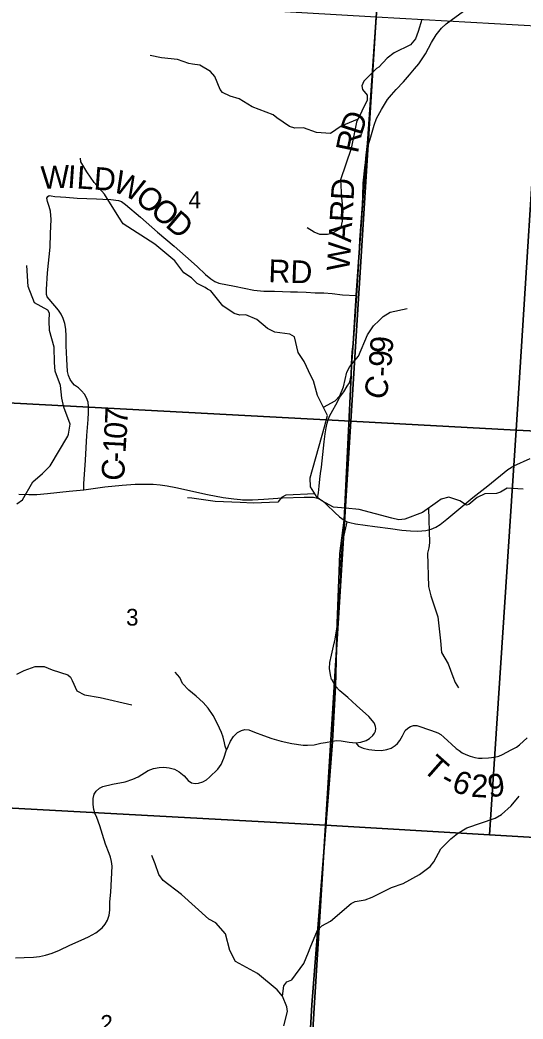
# Model space of a CAD drawing. Extents: x 1878108 to 2183446, y 146837 to 508383.
# Drawn here: x 2045522 to 2052165, y 348659 to 361848 of the extents above; entities that cross this region are included whole.
import ezdxf

# ---------------------------------------------------------------- set-up
doc = ezdxf.new("R2010")
doc.units = 0
for name, color, linetype in [('GM_X_County_Road', 7, 'Continuous'), ('GM_X_County_Road_Text', 7, 'Continuous'), ('GM_X_Minor_River', 7, 'Continuous'), ('GM_X_Section', 7, 'Continuous'), ('GM_X_Section_Text', 7, 'Continuous'), ('GM_X_State_Route', 7, 'Continuous'), ('GM_X_Township', 7, 'Continuous'), ('GM_X_Township_Road', 7, 'Continuous'), ('GM_X_Township_Road_Text', 7, 'Continuous'), ('GM_X_Township_ROW', 7, 'Continuous')]:
    doc.layers.add(name, color=color, linetype=linetype)

msp = doc.modelspace()

# ---------------------------------------------------------------- linework, layer by layer
at = {"layer": 'GM_X_County_Road'}
for points in [[(2050115, 360147), (2050122, 360189), (2050154, 360306), (2050199, 360460), (2050232, 360547), (2050295, 360666), (2050375, 360797), (2050429, 360861), (2050491, 360928), (2050587, 361033), (2050664, 361124), (2050731, 361202), (2050789, 361269), (2050876, 361401), (2050958, 361550), (2051020, 361653), (2051090, 361739), (2051151, 361798), (2051215, 361846), (2051377, 361964)], [(2050048, 359520), (2050055, 359694), (2050082, 359934), (2050097, 360034), (2050115, 360147)], [(2046364, 355647), (2046367, 355723), (2046387, 356036), (2046403, 356363), (2046424, 356573), (2046427, 356667), (2046429, 356746), (2046424, 356802), (2046402, 356860), (2046372, 356910), (2046333, 356954), (2046293, 356990), (2046244, 357029), (2046214, 357058), (2046184, 357100), (2046164, 357153), (2046151, 357207), (2046141, 357371), (2046134, 357545), (2046130, 357672), (2046128, 357765), (2046113, 357841), (2046094, 357908), (2046066, 357964), (2046032, 358019), (2045906, 358162), (2045883, 358193), (2045873, 358224), (2045872, 358290), (2045887, 358510), (2045919, 358849), (2045927, 359031), (2045932, 359215), (2045925, 359324), (2045907, 359385), (2045886, 359453), (2045877, 359494), (2045888, 359518), (2045907, 359530), (2045936, 359528), (2045981, 359518), (2046059, 359512), (2046129, 359510), (2046277, 359497), (2046531, 359485), (2046615, 359484), (2046720, 359477), (2046821, 359464), (2046864, 359453), (2046915, 359414), (2047112, 359245), (2047338, 359047), (2047557, 358863), (2047709, 358732), (2047862, 358593), (2047973, 358489), (2048041, 358432), (2048097, 358394), (2048147, 358375), (2048355, 358332), (2048610, 358282), (2048743, 358268), (2048883, 358267), (2049095, 358257), (2049189, 358257), (2049303, 358253), (2049418, 358246), (2049533, 358245), (2049644, 358236), (2049783, 358220), (2049963, 358209), (2049972, 358208)], [(2050005, 358838), (2050011, 358945), (2050044, 359411), (2050048, 359520)], [(2049972, 358208), (2049995, 358634), (2050002, 358765), (2050005, 358838)], [(2049898, 357201), (2049900, 357246), (2049909, 357346), (2049919, 357467), (2049935, 357701), (2049972, 358208)], [(2049452, 355537), (2049464, 355604), (2049472, 355695), (2049482, 355784), (2049491, 355861), (2049502, 355943), (2049540, 356278), (2049554, 356383), (2049565, 356463), (2049577, 356527), (2049590, 356571), (2049609, 356616), (2049652, 356695), (2049692, 356769), (2049748, 356867), (2049798, 356941), (2049843, 357012), (2049872, 357058), (2049887, 357110), (2049895, 357156), (2049898, 357201)], [(2049670, 353619), (2049678, 353653), (2049708, 353808), (2049723, 353970), (2049737, 354113), (2049753, 354388), (2049761, 354563), (2049767, 354776), (2049782, 354914), (2049803, 355046), (2049835, 355183), (2049844, 355222)], [(2049638, 353143), (2049623, 353205), (2049611, 353286), (2049613, 353364), (2049634, 353462), (2049670, 353619)], [(2049958, 352306), (2050021, 352314), (2050092, 352336), (2050138, 352364), (2050182, 352403), (2050205, 352433), (2050217, 352460), (2050220, 352495), (2050216, 352519), (2050210, 352547), (2050198, 352571), (2050129, 352653), (2049966, 352799), (2049851, 352903), (2049744, 352990), (2049687, 353053), (2049639, 353140), (2049638, 353143)], [(2048293, 352304), (2048303, 352326), (2048343, 352391), (2048396, 352441), (2048446, 352469), (2048492, 352480), (2048543, 352478), (2048620, 352447), (2048739, 352400), (2048847, 352361), (2048969, 352328), (2049111, 352296), (2049260, 352276), (2049321, 352276), (2049408, 352281), (2049494, 352299), (2049555, 352311)], [(2045463, 349468), (2045577, 349472), (2045699, 349474), (2045779, 349484), (2045859, 349501), (2045947, 349529), (2046046, 349569), (2046182, 349635), (2046329, 349702), (2046429, 349746), (2046522, 349797), (2046608, 349862), (2046649, 349910), (2046679, 349964), (2046700, 350030), (2046709, 350095), (2046710, 350208), (2046723, 350333), (2046730, 350507), (2046738, 350677), (2046732, 350740), (2046719, 350794), (2046699, 350845), (2046650, 350968), (2046612, 351094), (2046576, 351210), (2046535, 351319), (2046509, 351379), (2046496, 351425), (2046487, 351493), (2046487, 351570), (2046503, 351629), (2046528, 351669), (2046570, 351707), (2046617, 351728), (2046746, 351758), (2046912, 351792), (2047013, 351825), (2047081, 351857), (2047217, 351940), (2047287, 351966), (2047362, 351980), (2047421, 351982), (2047494, 351976), (2047564, 351956), (2047625, 351924), (2047689, 351868), (2047745, 351807), (2047788, 351779), (2047834, 351769), (2047879, 351775), (2047936, 351791), (2047983, 351818), (2048025, 351850), (2048135, 351958), (2048181, 352018), (2048213, 352101), (2048251, 352211), (2048266, 352242), (2048275, 352268), (2048293, 352304)], [(2049555, 352311), (2049648, 352329), (2049701, 352336), (2049763, 352332), (2049867, 352316), (2049958, 352306)]]:
    msp.add_lwpolyline(points, dxfattribs=at)
at = {"layer": 'GM_X_Minor_River'}
for points in [[(2050827, 361852), (2050780, 361694), (2050746, 361599), (2050677, 361519), (2050464, 361414), (2050372, 361344), (2050259, 361226), (2050229, 361208), (2050062, 361038), (2050038, 360980), (2050044, 360928), (2050109, 360853), (2050105, 360787), (2049968, 360498), (2049894, 360153), (2049754, 359736), (2049767, 359501), (2049787, 359338), (2049778, 359194), (2049753, 359097), (2049641, 359028), (2049585, 359018), (2049483, 359018), (2049407, 359047), (2049313, 359106)], [(2049976, 360532), (2049765, 360445), (2049621, 360351), (2049438, 360364), (2049268, 360425), (2049150, 360418), (2049080, 360442), (2048914, 360557), (2048864, 360596), (2048590, 360701), (2048416, 360805), (2048296, 360843), (2048196, 360892), (2048165, 360928), (2048093, 361101), (2048037, 361168), (2047896, 361253), (2047801, 361263), (2047753, 361274), (2047603, 361328), (2047391, 361347), (2047243, 361380)], [(2052167, 355652), (2051957, 355665), (2051868, 355613), (2051816, 355598), (2051660, 355594), (2051561, 355545), (2051451, 355451), (2051419, 355441), (2051331, 355501), (2051185, 355548), (2051083, 355521), (2051036, 355487), (2050839, 355347), (2050603, 355256), (2050527, 355250), (2050433, 355270), (2050002, 355385), (2049820, 355404), (2049664, 355417), (2049510, 355500), (2049446, 355542), (2049359, 355683), (2049355, 355802), (2049544, 356476), (2049585, 356626), (2049452, 356892), (2049400, 357083), (2049361, 357151), (2049273, 357338), (2049196, 357457), (2049148, 357664), (2049085, 357701), (2048888, 357726), (2048792, 357776), (2048649, 357895), (2048505, 357954), (2048425, 357953), (2048352, 357971), (2048201, 358074), (2048043, 358274), (2047999, 358294), (2047967, 358318), (2047863, 358369), (2047788, 358444), (2047686, 358510), (2047568, 358668), (2047303, 358890), (2046885, 359155), (2046827, 359243), (2046638, 359549), (2046503, 359701), (2046405, 359842), (2046324, 359973), (2046320, 360023)], [(2045481, 355460), (2045556, 355514), (2045691, 355752), (2045820, 355862), (2045920, 355964), (2046156, 356354), (2046164, 356382), (2046183, 356513), (2046100, 356738), (2046076, 356855), (2046055, 357022), (2045985, 357211), (2045976, 357327), (2045975, 357528), (2045910, 357747), (2045906, 357876), (2045911, 357978), (2045891, 358016), (2045715, 358112), (2045632, 358331), (2045613, 358606)], [(2049530, 356736), (2049686, 356820), (2049744, 356884), (2049795, 357003), (2049840, 357199), (2049878, 357273), (2049993, 357409), (2050110, 357692), (2050189, 357810), (2050265, 357880), (2050318, 357934), (2050412, 357990), (2050636, 358041)], [(2049414, 355591), (2049033, 355573), (2048975, 355543), (2048929, 355483), (2048602, 355468), (2048430, 355477), (2048101, 355491), (2047791, 355534), (2047733, 355541)], [(2050917, 355402), (2050932, 354947), (2050922, 354881), (2050905, 354808), (2050918, 354369), (2050947, 354244), (2051038, 353968), (2051075, 353653), (2051090, 353500), (2051178, 353349), (2051239, 353180), (2051267, 353100), (2051315, 353033)], [(2045480, 353210), (2045576, 353262), (2045723, 353312), (2045843, 353315), (2045945, 353267), (2046153, 353205), (2046189, 353171), (2046211, 353129), (2046274, 352990), (2046374, 352939), (2046580, 352902), (2046999, 352808)], [(2049007, 348569), (2049053, 348758), (2049048, 348822), (2048987, 348961), (2049005, 349098), (2049048, 349149), (2049114, 349175), (2049270, 349394), (2049334, 349543), (2049353, 349601), (2049453, 349833), (2049510, 349890), (2049622, 349951), (2049897, 350185), (2049949, 350212), (2050081, 350232), (2050173, 350269), (2050426, 350396), (2050583, 350450), (2050796, 350567), (2050937, 350675), (2050987, 350733), (2051081, 350905), (2051213, 351037), (2051301, 351110), (2051422, 351182), (2051797, 351310), (2051879, 351359), (2052007, 351473), (2052116, 351603)], [(2048987, 348963), (2048917, 349043), (2048658, 349262), (2048366, 349419), (2048292, 349563), (2048237, 349785), (2048109, 349930), (2048015, 349979), (2047654, 350302), (2047415, 350487), (2047356, 350567), (2047308, 350707), (2047263, 350817)]]:
    msp.add_lwpolyline(points, dxfattribs=at)
at = {"layer": 'GM_X_Section'}
for points in [[(2044786, 362212), (2050224, 361889), (2049893, 356551), (2044454, 356844), (2044518, 357870), (2044650, 360006)], [(2050224, 361889), (2052412, 361767), (2052076, 356435), (2049893, 356551)], [(2052412, 361767), (2054629, 361642), (2054256, 356327), (2052076, 356435)], [(2044454, 356844), (2049893, 356551), (2049557, 351218), (2044125, 351515), (2044378, 355609)], [(2052076, 356435), (2051723, 351091), (2049557, 351218), (2049893, 356551)], [(2054256, 356327), (2053887, 350963), (2051723, 351091), (2052076, 356435)], [(2044125, 351515), (2049557, 351218), (2049224, 345820), (2043762, 346145)], [(2051723, 351091), (2053887, 350963), (2054841, 350907), (2054872, 350905), (2054518, 345558), (2049224, 345820), (2049557, 351218)]]:
    msp.add_lwpolyline(points, close=True, dxfattribs=at)
at = {"layer": 'GM_X_State_Route'}
for points in [[(2049399, 355547), (2049452, 355537), (2049481, 355523), (2049511, 355503), (2049570, 355452), (2049680, 355348), (2049743, 355289), (2049804, 355245), (2049844, 355222), (2049878, 355212), (2049953, 355196), (2050209, 355163), (2050413, 355133), (2050566, 355111), (2050680, 355103), (2050776, 355098), (2050881, 355109), (2050950, 355126), (2051015, 355152), (2051070, 355189), (2051158, 355260), (2051504, 355546), (2051699, 355700), (2051965, 355912), (2052044, 355960), (2052259, 356060)], [(2045505, 355587), (2045639, 355582), (2045743, 355584), (2045884, 355595), (2046171, 355627), (2046364, 355647), (2046642, 355683), (2046872, 355708), (2047041, 355720), (2047151, 355722), (2047282, 355720), (2047373, 355712), (2047467, 355698), (2047579, 355677), (2048000, 355583), (2048205, 355544), (2048345, 355525), (2048434, 355518)], [(2048434, 355518), (2048461, 355515), (2048591, 355515), (2048741, 355523), (2048987, 355539), (2049276, 355550), (2049388, 355549), (2049399, 355547)]]:
    msp.add_lwpolyline(points, dxfattribs=at)
at = {"layer": 'GM_X_Township'}
for points in [[(2031084, 368365), (2039539, 367898), (2040525, 367845), (2042889, 367717), (2045115, 367597), (2048789, 367394), (2050600, 367297), (2050350, 363670), (2050111, 360216), (2050089, 360025), (2049963, 358214), (2049921, 357571), (2049907, 357468), (2049898, 357303), (2049895, 357156), (2049804, 355245), (2049744, 354805), (2049709, 353880), (2049687, 353053), (2049647, 352324), (2049375, 348847), (2049004, 342247)], [(2049004, 342247), (2049375, 348847), (2049647, 352324), (2049687, 353053), (2049709, 353880), (2049744, 354805), (2049804, 355245), (2049895, 357156), (2049898, 357303), (2049907, 357468), (2049921, 357571), (2049963, 358214), (2050089, 360025), (2050111, 360216), (2050350, 363670), (2050600, 367297), (2051071, 367290), (2053261, 367127)]]:
    msp.add_lwpolyline(points, dxfattribs=at)
at = {"layer": 'GM_X_Township_Road'}
msp.add_lwpolyline([(2049958, 352306), (2049991, 352263), (2050052, 352236), (2050129, 352219), (2050206, 352208), (2050297, 352206), (2050367, 352218), (2050424, 352237), (2050478, 352272), (2050507, 352298), (2050539, 352337), (2050572, 352398), (2050610, 352469), (2050645, 352499), (2050679, 352521), (2050718, 352535), (2050763, 352532), (2050957, 352470), (2051041, 352439), (2051078, 352417), (2051121, 352380), (2051171, 352331), (2051220, 352288), (2051283, 352231), (2051321, 352202), (2051360, 352174), (2051410, 352152), (2051469, 352131), (2051530, 352112), (2051576, 352104), (2051626, 352102), (2051710, 352106), (2051787, 352114), (2051845, 352129), (2051893, 352150), (2052009, 352214), (2052079, 352248), (2052119, 352281), (2052218, 352371)], dxfattribs=at)
at = {"layer": 'GM_X_Township_ROW'}
msp.add_lwpolyline([(2048251, 352211), (2048233, 352262), (2048221, 352306), (2048206, 352379), (2048182, 352441), (2048131, 352558), (2048072, 352666), (2048005, 352764), (2047939, 352837), (2047850, 352921), (2047754, 353002), (2047669, 353087), (2047631, 353168), (2047571, 353238)], dxfattribs=at)

# ---------------------------------------------------------------- texts
at = {"layer": 'GM_X_County_Road_Text'}
for s, rotation, p in [('D', 72.1779, (2050031, 360311)), ('R', 78.0922, (2049983, 360078)), ('W', 2.6016, (2045804, 359617)), ('I', 356.1485, (2046142, 359633)), ('L', 356.1358, (2046265, 359625)), ('D', 355.7779, (2046489, 359610)), ('W', 336.5297, (2046726, 359597)), ('WARD', 86.6731, (2049872, 358527)), ('O', 319.6958, (2047025, 359470)), ('O', 319.5564, (2047227, 359300)), ('D', 319.5485, (2047428, 359129)), ('RD', 358.041, (2048799, 358388)), ('9', 85.8703, (2050440, 357441)), ('9', 85.7342, (2050426, 357256)), ('C', 71.702, (2050328, 356811)), ('-', 87.8436, (2050422, 357136)), ('7', 87.1832, (2046941, 356500)), ('0', 85.4176, (2046926, 356307)), ('1', 86.8607, (2046916, 356126)), ('-', 87.0254, (2046910, 356004)), ('C', 86.6485, (2046895, 355758))]:
    msp.add_text(s, height=300, rotation=rotation, dxfattribs=at).set_placement(p)
at = {"layer": 'GM_X_Section_Text'}
for s, p in [('4', (2047748, 359363)), ('3', (2046923, 353853)), ('2', (2046584, 348491))]:
    msp.add_text(s, height=221, rotation=0, dxfattribs=at).set_placement(p)
at = {"layer": 'GM_X_Township_Road_Text'}
for s, rotation, p in [('T', 318.5206, (2050826, 351946)), ('6', 340.2019, (2051208, 351675)), ('2', 356.5316, (2051473, 351594)), ('9', 7.2282, (2051718, 351584)), ('-', 331.2098, (2051053, 351755))]:
    msp.add_text(s, height=300, rotation=rotation, dxfattribs=at).set_placement(p)

doc.saveas('drawing.dxf')
